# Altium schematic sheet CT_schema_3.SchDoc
size 289 x 159 mm
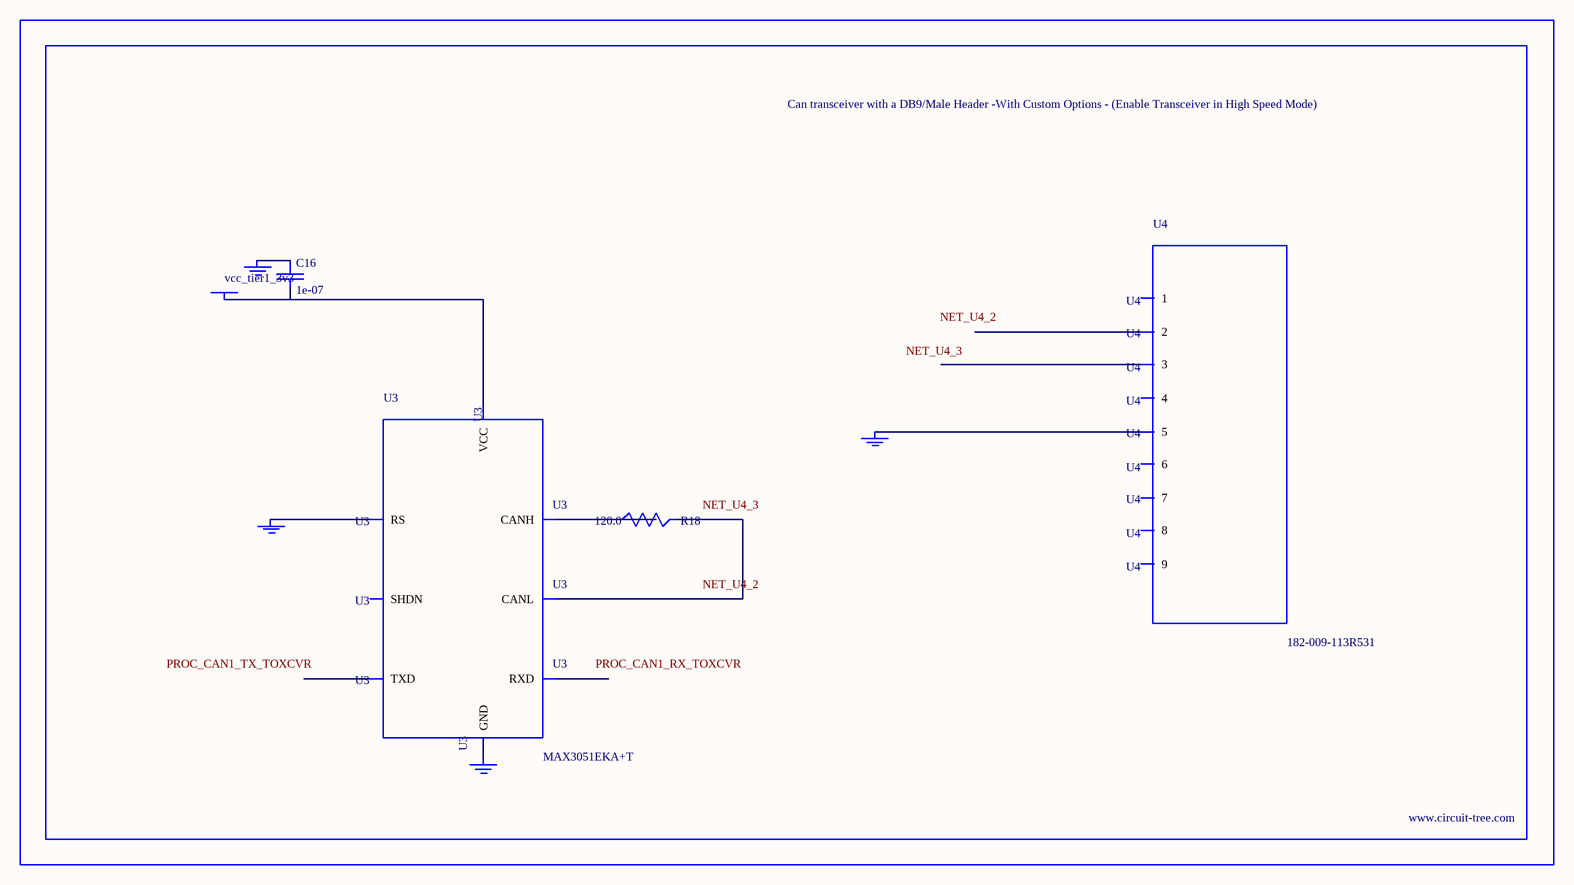
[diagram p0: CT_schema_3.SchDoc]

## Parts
BORDER2  (no value)
C16  1e-07  [C0402]
GND_INSTANCE_2_0  (no value)
GND_INSTANCE_2_1  (no value)
GND_INSTANCE_2_2  (no value)
GND_INSTANCE_2_3  (no value)
POWER_INSTANCE_2_0  vcc_tier1_3v3
R18  120.0  [R0603]
U3  MAX3051EKA+T  [SOT-23-8]
U4  182-009-113R531  [182-009-MALE]

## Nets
NetC16_1: C16.1 GND_INSTANCE_2_0.0(GND)
NetC16_2: C16.2 POWER_INSTANCE_2_0.0(PWR) U3.3(VCC)
NetGND_INSTANCE_2_1_0: GND_INSTANCE_2_1.0(GND) U3.8(RS)
NetGND_INSTANCE_2_2_0: GND_INSTANCE_2_2.0(GND) U3.2(GND)
NetGND_INSTANCE_2_3_0: GND_INSTANCE_2_3.0(GND) U4.5
NetR18_1: R18.1 U3.7(CANH)
NetR18_2: R18.2 U3.6(CANL)

Not connected (* = marked no-connect by the designer): U3 1(TXD) 4(RXD) 5(SHDN); U4 1 2 3 4 6 7 8 9

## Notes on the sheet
- Labels drawn without touching a wire or pin: NET_U4_2, NET_U4_3, PROC_CAN1_RX_TOXCVR, PROC_CAN1_TX_TOXCVR

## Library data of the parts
BORDER2 = BORDER_PAGE2
C16 = C0402C104K3RACTU
GND_INSTANCE_2_0-GND_INSTANCE_2_3 = GND
POWER_INSTANCE_2_0 = PWR
R18 = RC0603JR-07120RL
